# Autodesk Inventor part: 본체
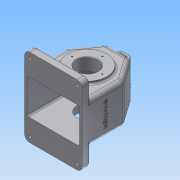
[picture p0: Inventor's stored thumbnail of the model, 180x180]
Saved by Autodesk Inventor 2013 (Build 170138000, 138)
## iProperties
Created: 2016-12
Part Number: 본체
Material: 알루미늄 6061
Document SubType Name: Modeling
Designer: Administrator
Density: 2.71 g/cm^3
Mass: 1067.34 g
Surface Area: 1137.96 cm^2
Volume: 393.853 cm^3
Author: Administrator
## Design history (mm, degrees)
sketch "스케치1"
  geometry: L1 (-55, -65)-(-55, 15); L2 (-55, 15)-(-23.491, 60); L3 (-23.491, 60)-(23.491, 60); L4 (23.491, 60)-(55, 15); L5 (55, 15)-(55, -65); L6 (55, -65)-(-55, -65); 1 further point
  constraints: 12 end point, 3 parallel, 1 perpendicular, 1 vertical
  dimensions: "d0" = 110 distance of L5.end L1.start; "d2" = 80 distance of L4.end L5.end; "d3" = 125 distance between parallel lines of L6 L3; "d4" = 65 distance from line of L6 point (0, 0); "d5" = 55 distance from line of point (0, 0) L1; "d6" = 35 deg angle of L2 L1; "d7" = 35 deg angle of L4 L5
extrude "돌출1" new body sketch "스케치1" stored distance "d8" = 77; taper "d9" = 0 deg
fillet "모깎기1" dims "d10" = 10
fillet "모깎기2" dims "d11" = 8
feature "쉘1" dims "d12" = 5
sketch "스케치2"
  geometry: L1 (94, 0)-(0, 0) reference; L2 (102, 69)-(102, 8) reference; L3 (0, 77)-(94, 77) reference; L4 (-8, 8)-(-8, 69) reference; L5 (-8, 113.5)-(102, 113.5); L6 (102, 113.5)-(102, -36.5); L7 (102, -36.5)-(-8, -36.5); L8 (-8, -36.5)-(-8, 113.5); A1 r 8 centre (0, 8) between (-8, 8) and (0, 0) reference; A2 r 8 centre (94, 8) between (94, 0) and (102, 8) reference; A3 r 8 centre (94, 69) between (102, 69) and (94, 77) reference; A4 r 8 centre (0, 69) between (0, 77) and (-8, 69) reference; 1 further point
  constraints: 8 end point, 2 parallel, 1 horizontal, 1 perpendicular
  dimensions: "d15" = 150 distance of L5.end L6.end; "d17" = 110 distance of L5.start L5.end; "d18" = 55 distance from line of L8 point (47, 38.5); "d19" = 75 distance from line of L5 point (47, 38.5)
extrude "돌출2" join sketch "스케치2" distance "d20" = 15; taper "d21" = 0 deg
fillet "모깎기3" dims "d22" = 10
sketch "스케치3"
  geometry: C1 r 37.5 at (0, 0); 1 further point
  constraints: 1 centre point, 1 coincident
  dimensions: "d23" = 75 diameter of C1
extrude "돌출3" join sketch "스케치3" distance "d24" = 5; taper "d25" = 0 deg
sketch "스케치4"
  geometry: C1 r 31 at (0, 0); 1 further point
  constraints: 1 centre point, 1 coincident
  dimensions: "d26" = 62 diameter of C1
extrude "돌출4" join sketch "스케치4" distance "d27" = 10; taper "d28" = 0 deg
node "작업 평면1"
sketch "스케치5"
  geometry: C1 r 27 at (0, 0); 1 further point
  constraints: 1 centre point, 1 coincident
  dimensions: "d30" = 54 diameter of C1
extrude "돌출5" join sketch "스케치5" stored distance "d31" = 10; taper "d32" = 45 deg
sketch "스케치6"
  geometry: C1 r 37.5 at (0, 0) reference; C2 r 20 at (0, 0)
  constraints: 1 centre point, 1 coincident
  dimensions: "d33" = 40 diameter of C2
extrude "돌출6" cut sketch "스케치6" stored distance "d34" = 10; taper "d35" = 0 deg
chamfer "모따기1" distance "d36" = 1; stored, may be unused: second distance "d37" = 2, angle "d38" = 45 deg
fillet "모깎기4" dims "d39" = 3
fillet "모깎기5" dims "d40" = 3
fillet "모깎기6" dims "d41" = 3
sketch "스케치7"
  geometry: L1 (99, 26.5)-(99, 1.798) reference; L2 (2, 33.5)-(92, 33.5) reference; L3 (-5, 1.798)-(-5, 26.5) reference; L4 (94, 3)-(0, 3) reference; A1 r 7 centre (2, -103.5) between (-5, -103.5) and (2, -110.5) reference; A2 r 7 centre (92, -103.5) between (92, -110.5) and (99, -103.5) reference; A3 r 11 centre (94, -8) between (99, 1.798) and (94, 3) reference; A4 r 7 centre (92, 26.5) between (99, 26.5) and (92, 33.5) reference; A5 r 7 centre (2, 26.5) between (2, 33.5) and (-5, 26.5) reference; A6 r 11 centre (0, -8) between (0, 3) and (-5, 1.798) reference; 5 further points
  constraints: 4 coincident
hole "구멍1" sketch "스케치7" at (2, -103.5), (92, -103.5), (2, 26.5), (92, 26.5) diameter "d42" = 5; stored, may be unused: countersink angle "d46" = 90 deg, drill point angle "d48" = 118 deg; dims "d43" = 6, "d44" = 12, "d45" = 5, "d47" = 8
node "작업 평면2"
sketch "스케치8"
  geometry: L1 (-12.5, 59.994)-(-12.5, 67); L2 (-4.5, 75)-(4.5, 75); L3 (12.5, 67)-(12.5, 59.994); L4 (55, 11.847)-(55, -65) reference; L5 (55, -65)-(50, -65) reference; L6 (50, -65)-(50, 11.847) reference; L7 (49.096, 14.715)-(22.381, 52.868) reference; L8 (18.285, 55)-(-18.285, 55) reference; L9 (-22.381, 52.868)-(-49.096, 14.715) reference; L10 (-50, 11.847)-(-50, -65) reference; L11 (-50, -65)-(-55, -65) reference; L12 (-55, -65)-(-55, 11.847) reference; L13 (-53.192, 17.583)-(-26.477, 55.736) reference; L14 (-18.285, 60)-(18.285, 60) reference; L15 (26.477, 55.736)-(53.192, 17.583) reference; L16 (47, -65)-(-47, -65) reference; A1 r 5 centre (45, 11.847) between (50, 11.847) and (49.096, 14.715) reference; A2 r 5 centre (18.285, 50) between (22.381, 52.868) and (18.285, 55) reference; A3 r 5 centre (-18.285, 50) between (-18.285, 55) and (-22.381, 52.868) reference; A4 r 5 centre (-45, 11.847) between (-49.096, 14.715) and (-50, 11.847) reference; A5 r 10 centre (-45, 11.847) between (-53.192, 17.583) and (-55, 11.847) reference; A6 r 10 centre (-18.285, 50) between (-18.285, 60) and (-26.477, 55.736) reference; A7 r 10 centre (18.285, 50) between (26.477, 55.736) and (18.285, 60) reference; A8 r 10 centre (45, 11.847) between (55, 11.847) and (53.192, 17.583) reference; A9 r 8 centre (4.5, 67) between (12.5, 67) and (4.5, 75); A10 r 8 centre (-4.5, 67) between (-4.5, 75) and (-12.5, 67); 3 further points
  constraints: 6 end point, 4 point on circle, 4 point on line, 4 tangent, 2 centre point, 1 equal radius, 1 parallel, 1 perpendicular, 1 vertical
  dimensions: "d50" = 140 distance between parallel lines of L16 L2; "d51" = 25 distance of point (-12.5, 75) point (12.5, 75); "d52" = 12.5 distance from line of point (0, 0) L1; "d59" = 8 radius of A9
feature "리브1" sketch "스케치8" dims "d53" = 5, "d54" = 8, "d55" = 0, "d56" = 0, "d57" = 1, "d58" = 1
fillet "모깎기7" dims "d60" = 1
fillet "모깎기9" dims "d62" = 1
fillet "모깎기10" dims "d63" = 1
sketch "스케치9"
  geometry: C1 r 31 at (0, 0) reference; 1 further point
  constraints: 1 vertical alignment
  dimensions: "d64" = 26 distance of C1.centre point (0, 26)
hole "구멍2" sketch "스케치9" at (0, 26) diameter "d65" = 2.459; stored, may be unused: countersink angle "d69" = 90 deg, drill point angle "d71" = 118 deg; dims "d66" = 6, "d67" = 12, "d68" = 5, "d70" = 8
sketch "스케치10"
  geometry: C1 r 37.5 at (0, 0) reference; 1 further point
  constraints: 1 vertical alignment
  dimensions: "d75" = 29 distance of C1.centre point (0, 29)
hole "구멍3" sketch "스케치10" at (0, 29) diameter "d76" = 2.459; stored, may be unused: countersink angle "d80" = 90 deg, drill point angle "d82" = 118 deg; dims "d77" = 6, "d78" = 12, "d79" = 5, "d81" = 8
sketch "스케치11"
  geometry: L1 (-34.5, -76.847)-(95.5, -76.847) reference; L2 (-8, 0)-(-8, -58.847) reference; 2 further points
  constraints: 1 other
  dimensions: "d86" = 38.5 distance from line of L2 point (30.5, -31.847); "d87" = 45 distance from line of L1 point (30.5, -31.847)
feature "엠보싱1" sketch "스케치11" dims "d0" = 110, "d2" = 80, "d3" = 125, "d4" = 65, "d5" = 55, "d6" = 35 deg, "d7" = 35 deg, "d88" = 0.5, "d89" = 0
fillet "모깎기11" dims "d90" = 3
node "솔리드1"
mirror "대칭2"
pattern_circular "원형 패턴1" dims angle "d73" = 360 deg
pattern_circular "원형 패턴2" dims angle "d84" = 360 deg
node "투영된 루프1"
node "절단 모서리 투영1"
other parameters: "d29" = -24, "d49" = 18
